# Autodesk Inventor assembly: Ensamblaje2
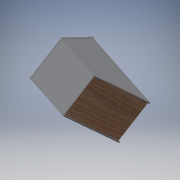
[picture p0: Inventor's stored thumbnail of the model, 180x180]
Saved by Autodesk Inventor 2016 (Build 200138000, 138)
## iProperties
Created: 2016-06
Part Number: Ensamblaje2
Material: Genérico
Document SubType Name: Assembly
Designer: adm
Author: adm
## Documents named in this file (5)
- C:\Users\adm\Desktop\recepcion 2\Ensamblaje2.iam
- C:\Users\adm\Desktop\recepcion 2\parte porterior.ipt
- C:\Users\adm\Desktop\recepcion 2\laterales(2).ipt
- C:\Users\adm\Desktop\recepcion 2\lado inclinado.ipt
- C:\Users\adm\Desktop\recepcion 2\base.ipt
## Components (5 placed, 4 different names)
1. parte porterior:1 — Coincidencia:1, Coincidencia:2, Coincidencia:3, Coincidencia:4, Coincidencia:5, Nivelación:2, Coincidencia:10, Nivelación:3, Coincidencia:11
2. laterales(2):1 — Coincidencia:1, Coincidencia:2, Coincidencia:3, Coincidencia:6, Coincidencia:7, Coincidencia:8
3. laterales(2):2 — Coincidencia:4, Coincidencia:5, Nivelación:1, Coincidencia:9
4. lado inclinado:1 — Coincidencia:6, Coincidencia:7, Coincidencia:8, Nivelación:1, Coincidencia:9
5. base:1 — Nivelación:2, Coincidencia:10, Nivelación:3, Coincidencia:11
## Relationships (14: Mate 11, Flush 3)
- Coincidencia:1 [Mate]: parte porterior:1 ↔ laterales(2):1
- Coincidencia:2 [Mate]: parte porterior:1 ↔ laterales(2):1
- Coincidencia:3 [Mate]: parte porterior:1 ↔ laterales(2):1
- Coincidencia:4 [Mate]: parte porterior:1 ↔ laterales(2):2
- Coincidencia:5 [Mate]: parte porterior:1 ↔ laterales(2):2
- Coincidencia:6 [Mate]: laterales(2):1 ↔ lado inclinado:1
- Coincidencia:7 [Mate]: laterales(2):1 ↔ lado inclinado:1
- Coincidencia:8 [Mate]: laterales(2):1 ↔ lado inclinado:1
- Nivelación:1 [Flush]: laterales(2):2 ↔ lado inclinado:1
- Coincidencia:9 [Mate]: laterales(2):2 ↔ lado inclinado:1
- Nivelación:2 [Flush]: parte porterior:1 ↔ base:1
- Coincidencia:10 [Mate]: parte porterior:1 ↔ base:1
- Nivelación:3 [Flush]: parte porterior:1 ↔ base:1
- Coincidencia:11 [Mate]: parte porterior:1 ↔ base:1
